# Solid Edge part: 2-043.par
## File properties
Title: O-Ring 2-043
Subject: seal
Author: Dan
Template: Normal.par
Last saved by: Dan
Revision: 128
Application: Solid Edge
Category: parts
Density: 0 kg/mm^3
Accuracy: 0.99
Document Number: P52-009
Project Name: seal
Material: nitrile
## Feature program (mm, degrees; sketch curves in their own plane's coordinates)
sketch for "unnamed RevolvedProtrusion 1" plane through (0, 0, 0) normal (0, -1, 0) x-axis (1, 0, 0)
  circle centre (0, 47.89) radius 0.89
revolve "unnamed RevolvedProtrusion 1" add full turn 360 deg
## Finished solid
Body 1: solid body, 1 face, 0 edges, 0 vertices.
  Faces by surface: torus 1
Toroidal faces (ring radius, tube radius in mm): R47.89 r0.89 x1
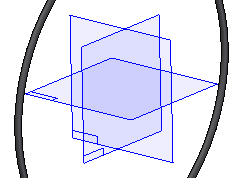
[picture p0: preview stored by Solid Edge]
